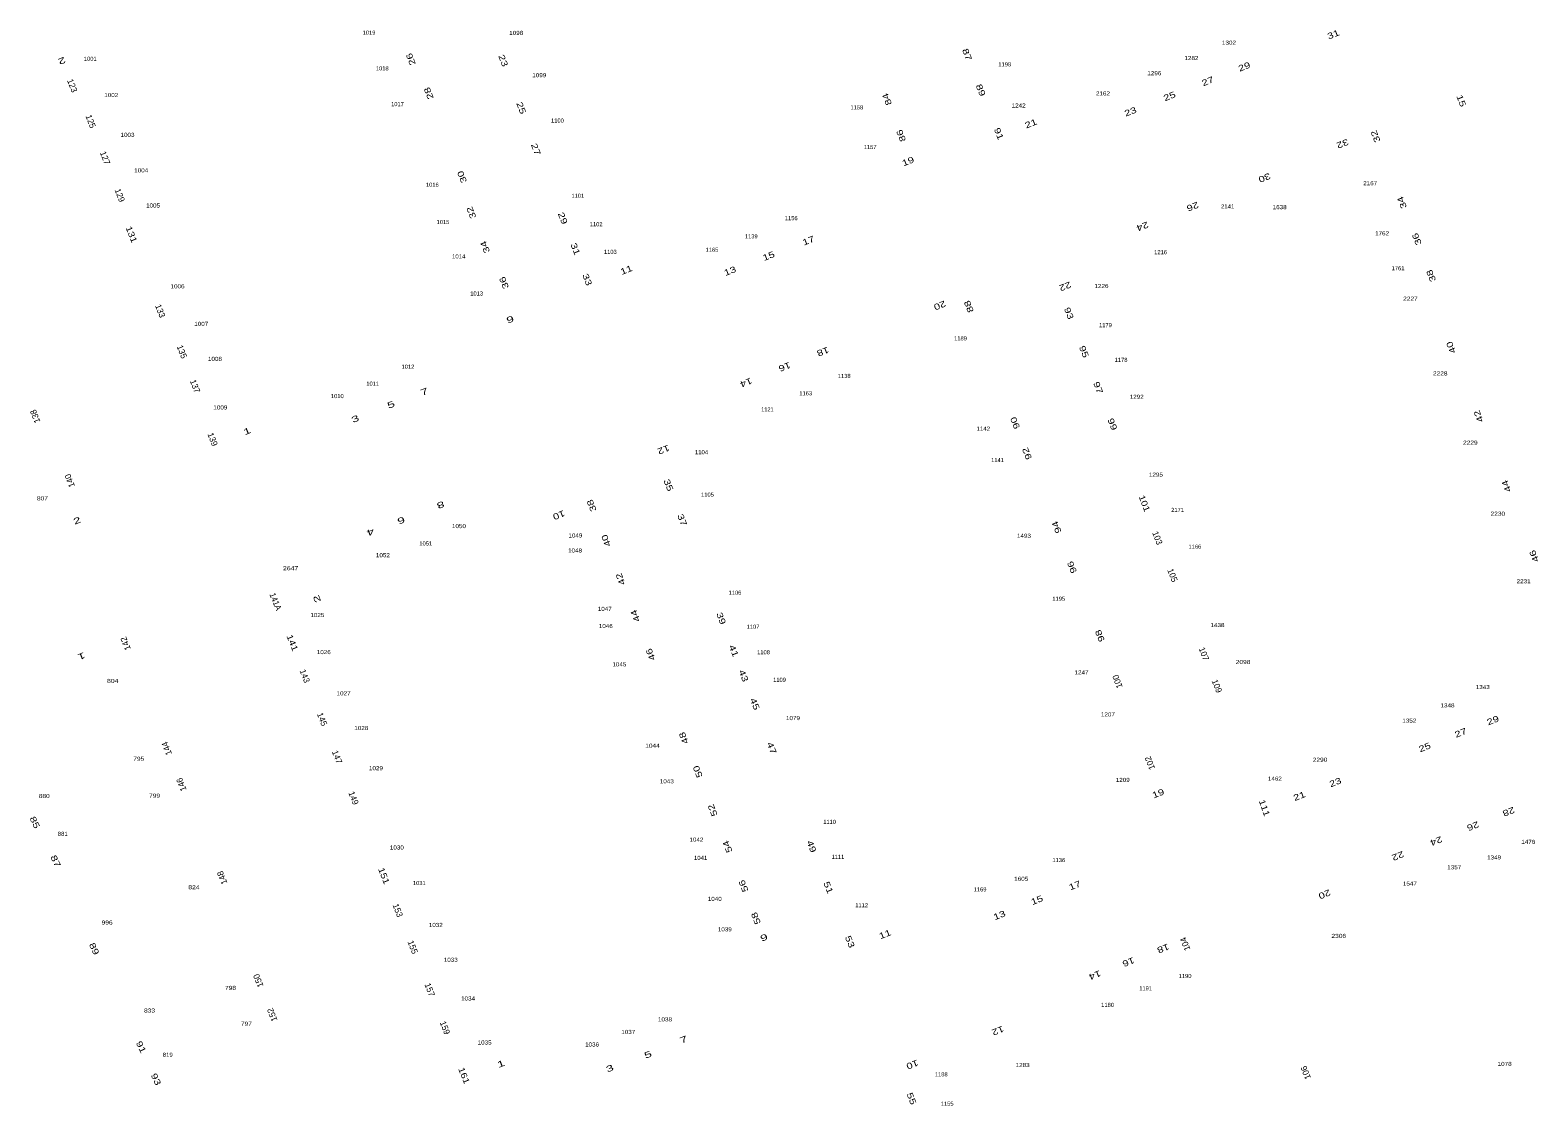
# Model space of a CAD drawing. Extents: x -828673 to -815583, y -1077737 to -1063807.
# Drawn here: x -821441.6 to -821072.8, y -1072104.4 to -1071841.3 of the extents above; entities that cross this region are included whole.
import ezdxf
from ezdxf.enums import TextEntityAlignment as Align

# ---------------------------------------------------------------- set-up
doc = ezdxf.new("R2010")
doc.units = 0
doc.header["$LTSCALE"] = 0.4
doc.layers.add('1', color=7, linetype='Continuous')
doc.layers.add('2', color=7, linetype='Continuous')

msp = doc.modelspace()

# ---------------------------------------------------------------- texts
at = {"layer": '1'}
for s, width, p in [('1019', 1.05, (-821358.676, -1071842.438)), ('1098', 1.15, (-821322.681, -1071842.501)), ('1302', 1.15, (-821148.373, -1071844.888)), ('1001', 1.05, (-821426.855, -1071848.838)), ('1018', 1.05, (-821355.448, -1071851.177)), ('1198', 1.05, (-821203.208, -1071850.196)), ('1282', 1.15, (-821157.545, -1071848.648)), ('1099', 1.15, (-821317.042, -1071852.844)), ('1296', 1.15, (-821166.627, -1071852.363)), ('1002', 1.15, (-821421.722, -1071857.701)), ('2162', 1.15, (-821179.183, -1071857.314)), ('1017', 1.05, (-821351.728, -1071859.925)), ('1158', 1.05, (-821239.376, -1071860.714)), ('1242', 1.15, (-821199.808, -1071860.268)), ('1100', 1.05, (-821312.602, -1071863.939)), ('1003', 1.15, (-821417.748, -1071867.433)), ('1157', 1.05, (-821236.132, -1071870.425)), ('1004', 1.15, (-821414.395, -1071876.13)), ('1016', 1.05, (-821343.2, -1071879.639)), ('2167', 1.15, (-821113.836, -1071879.273)), ('1005', 1.15, (-821411.5, -1071884.718)), ('1156', 1.05, (-821255.43, -1071887.812)), ('2141', 1.1, (-821148.692, -1071884.94)), ('1638', 1.15, (-821135.975, -1071885.124)), ('1015', 1.05, (-821340.598, -1071888.764)), ('1102', 1.05, (-821303.131, -1071889.296)), ('1762', 1.15, (-821110.933, -1071891.535)), ('1165', 1.05, (-821274.809, -1071895.536)), ('1139', 1.05, (-821265.198, -1071892.245)), ('1014', 1.1, (-821336.749, -1071897.171)), ('1103', 1.05, (-821299.671, -1071896.049)), ('1216', 1.05, (-821165.095, -1071896.142)), ('1761', 1.05, (-821107.016, -1071900.063)), ('1006', 1.15, (-821405.508, -1071904.477)), ('1013', 1.05, (-821332.361, -1071906.239)), ('1226', 1.15, (-821179.548, -1071904.408)), ('2227', 1.2, (-821103.984, -1071907.495)), ('1007', 1.15, (-821399.713, -1071913.671)), ('1179', 1.05, (-821178.581, -1071913.983)), ('1189', 1.05, (-821214.032, -1071917.207)), ('1008', 1.15, (-821396.369, -1071922.226)), ('1012', 1.05, (-821349.164, -1071924.144)), ('1178', 1.05, (-821174.757, -1071922.465)), ('1138', 1.05, (-821242.466, -1071926.4)), ('2228', 1.2, (-821096.704, -1071925.796)), ('1010', 1.05, (-821366.44, -1071931.337)), ('1163', 1.05, (-821251.869, -1071930.649)), ('1292', 1.15, (-821170.932, -1071931.5)), ('1009', 1.15, (-821395.044, -1071934.112)), ('1142', 1.1, (-821208.442, -1071939.285)), ('2229', 1.2, (-821089.341, -1071942.722)), ('1104', 1.1, (-821277.375, -1071945.06)), ('1295', 1.15, (-821166.236, -1071950.549)), ('807', 1.2, (-821438.554, -1071956.347)), ('1105', 1.05, (-821275.916, -1071955.437)), ('2171', 1.05, (-821160.938, -1071959.169)), ('2230', 1.2, (-821082.614, -1071960.101)), ('1050', 1.15, (-821336.695, -1071963.133)), ('1049', 1.15, (-821308.221, -1071965.424)), ('1493', 1.15, (-821198.51, -1071965.495)), ('1051', 1.05, (-821344.808, -1071967.378)), ('1048', 1.15, (-821308.299, -1071969.09)), ('1166', 1.05, (-821156.699, -1071968.158)), ('1052', 1.15, (-821355.291, -1071970.25)), ('2647', 1.25, (-821377.862, -1071973.433)), ('2231', 1.15, (-821076.307, -1071976.618)), ('1106', 1.05, (-821269.183, -1071979.421)), ('1047', 1.15, (-821301.031, -1071983.375)), ('1195', 1.05, (-821189.997, -1071980.891)), ('1025', 1.15, (-821371.31, -1071984.893)), ('1046', 1.15, (-821300.782, -1071987.579)), ('1107', 1.05, (-821264.765, -1071987.747)), ('1438', 1.15, (-821151.179, -1071987.34)), ('1026', 1.15, (-821369.749, -1071993.951)), ('1108', 1.05, (-821262.201, -1071993.981)), ('1045', 1.15, (-821297.454, -1071996.943)), ('1247', 1.15, (-821184.436, -1071998.922)), ('2098', 1.2, (-821144.913, -1071996.375)), ('804', 1.25, (-821421.362, -1072001.001)), ('1109', 1.05, (-821258.297, -1072000.728)), ('1343', 1.15, (-821086.3, -1072002.502)), ('1027', 1.15, (-821364.891, -1072004.029)), ('1207', 1.15, (-821177.976, -1072009.186)), ('1348', 1.15, (-821094.916, -1072006.973)), ('1028', 1.15, (-821360.564, -1072012.519)), ('1079', 1.15, (-821254.991, -1072010.09)), ('1352', 1.15, (-821104.269, -1072010.707)), ('1044', 1.2, (-821289.353, -1072016.842)), ('795', 1.2, (-821415.002, -1072020.029)), ('2290', 1.2, (-821126.092, -1072020.284)), ('1029', 1.15, (-821356.986, -1072022.342)), ('1043', 1.15, (-821285.858, -1072025.541)), ('1209', 1.15, (-821174.348, -1072025.205)), ('1462', 1.15, (-821137.15, -1072024.894)), ('880', 1.2, (-821438.114, -1072029.147)), ('799', 1.2, (-821411.121, -1072029.06)), ('881', 1.1, (-821433.579, -1072038.397)), ('1030', 1.15, (-821351.878, -1072041.738)), ('1042', 1.15, (-821278.619, -1072039.816)), ('1476', 1.15, (-821075.162, -1072040.36)), ('1041', 1.1, (-821277.584, -1072044.274)), ('1111', 0.9, (-821244, -1072044.024)), ('1136', 1.05, (-821189.994, -1072044.815)), ('1357', 1.15, (-821093.279, -1072046.576)), ('1349', 1.15, (-821083.539, -1072044.17)), ('1031', 1.05, (-821346.387, -1072050.436)), ('1605', 1.15, (-821199.183, -1072049.392)), ('824', 1.25, (-821401.491, -1072051.458)), ('1169', 1.05, (-821209.239, -1072051.996)), ('1547', 1.15, (-821104.125, -1072050.57)), ('1040', 1.15, (-821274.131, -1072054.305)), ('996', 1.2, (-821422.728, -1072060.096)), ('1032', 1.15, (-821342.351, -1072060.675)), ('1039', 1.15, (-821271.677, -1072061.755)), ('2306', 1.2, (-821121.52, -1072063.362)), ('1033', 1.15, (-821338.691, -1072069.207)), ('798', 1.2, (-821392.557, -1072076.079)), ('1190', 1.05, (-821159.105, -1072073.164)), ('1034', 1.15, (-821334.466, -1072078.662)), ('833', 1.2, (-821412.355, -1072081.62)), ('1180', 1.05, (-821178.056, -1072080.233)), ('797', 1.2, (-821388.676, -1072084.848)), ('1037', 1.15, (-821295.281, -1072086.847)), ('1038', 1.15, (-821286.3, -1072083.77)), ('1035', 1.15, (-821330.406, -1072089.432)), ('1036', 1.15, (-821304.139, -1072089.925)), ('819', 1.1, (-821407.907, -1072092.44)), ('1078', 1.15, (-821080.947, -1072094.671)), ('1188', 1.05, (-821218.736, -1072097.216)), ('1283', 1.15, (-821198.834, -1072094.948)), ('1155', 1.05, (-821217.284, -1072104.417))]:
    msp.add_text(s, height=1, dxfattribs=dict(at, width=width)).set_placement(p, align=Align.CENTER)
for s, p in [('1101', (-821307.609, -1071882.334)), ('1011', (-821357.789, -1071928.273)), ('1121', (-821261.254, -1071934.595)), ('1141', (-821204.978, -1071946.991)), ('1110', (-821246.042, -1072035.47)), ('1112', (-821238.203, -1072055.86)), ('1191', (-821168.746, -1072076.17))]:
    msp.add_text(s, height=1, dxfattribs=at).set_placement(p, align=Align.CENTER)
at = {"layer": '2'}
for s, rotation, width, p in [('31', 21.91, 1.35, (-821122.5759, -1071843.0675)), ('87', 291.612, 1.35, (-821213.1119, -1071847.5658)), ('2', 201.854, 1.65, (-821434.0593, -1071848.1341)), ('26', 111.307, 1.35, (-821347.7676, -1071848.1805)), ('23', 291.4, 1.35, (-821326.5503, -1071849.0453)), ('29', 21.878, 1.35, (-821144.3525, -1071850.9592)), ('27', 21.908, 1.35, (-821153.2858, -1071854.5225)), ('28', 111.366, 1.35, (-821343.3849, -1071856.5152)), ('84', 111.699, 1.35, (-821231.3212, -1071857.9743)), ('89', 291.69, 1.35, (-821209.77, -1071856.2768)), ('25', 21.865, 1.35, (-821162.6348, -1071858.1937)), ('15', 291.488, 1.35, (-821092.251, -1071858.8678)), ('25', 291.631, 1.35, (-821322.1484, -1071860.6285)), ('23', 21.315, 1.35, (-821172.2096, -1071861.9563)), ('21', 21.878, 1.35, (-821196.5365, -1071864.8572)), ('86', 111.334, 1.35, (-821227.8612, -1071866.8719)), ('91', 291.552, 1.35, (-821205.3375, -1071866.943)), ('32', 201.845, 1.35, (-821120.8469, -1071868.415)), ('32', 111.531, 1.35, (-821111.8282, -1071867.0482)), ('27', 291.657, 1.35, (-821318.5638, -1071870.7392)), ('19', 21.763, 1.35, (-821226.5776, -1071874.1151)), ('30', 111.53, 1.35, (-821335.2402, -1071876.9522)), ('30', 201.754, 1.35, (-821139.9455, -1071876.7557)), ('26', 201.801, 1.35, (-821157.524, -1071883.7998)), ('34', 111.633, 1.35, (-821105.3786, -1071883.2295)), ('32', 111.778, 1.35, (-821332.9712, -1071885.7028)), ('29', 291.829, 1.35, (-821311.9884, -1071887.5971)), ('131', 291.645, 1.25, (-821417.4698, -1071891.5749)), ('24', 201.251, 1.35, (-821169.7807, -1071888.638)), ('36', 111.567, 1.35, (-821101.7389, -1071892.1722)), ('34', 111.848, 1.35, (-821329.6191, -1071894.1101)), ('31', 291.488, 1.35, (-821308.899, -1071895.1208)), ('17', 21.485, 1.35, (-821250.9452, -1071893.5011)), ('15', 21.571, 1.35, (-821260.6842, -1071897.263)), ('36', 111.506, 1.35, (-821324.9804, -1071902.8485)), ('33', 291.674, 1.35, (-821306.0084, -1071902.616)), ('11', 21.48, 1.35, (-821295.4761, -1071900.6742)), ('13', 21.501, 1.35, (-821270.1244, -1071900.9377)), ('38', 111.807, 1.35, (-821098.2459, -1071901.1261)), ('22', 201.151, 1.35, (-821188.7014, -1071903.3115)), ('20', 201.294, 1.35, (-821219.3451, -1071907.963)), ('88', 112.213, 1.35, (-821211.3021, -1071908.6645)), ('93', 291.259, 1.35, (-821188.2008, -1071910.8476)), ('9', 19.822, 1.65, (-821323.9123, -1071912.7973)), ('18', 201.492, 1.35, (-821247.9327, -1071919.2571)), ('95', 291.746, 1.35, (-821184.5125, -1071920.2386)), ('40', 112.82, 1.35, (-821093.3572, -1071918.6659)), ('16', 201.364, 1.35, (-821257.2968, -1071922.9929)), ('14', 201.737, 1.35, (-821266.7217, -1071926.8243)), ('97', 291.522, 1.35, (-821181.0582, -1071929.0414)), ('7', 20.452, 1.65, (-821344.8966, -1071930.4492)), ('5', 21.756, 1.65, (-821353.0265, -1071933.6146)), ('42', 111.621, 1.35, (-821086.6333, -1071935.4983)), ('1', 22.65, 1.65, (-821388.2288, -1071940.0956)), ('3', 22.629, 1.65, (-821361.7636, -1071937.0868)), ('90', 111.497, 1.35, (-821199.9882, -1071937.1283)), ('99', 291.476, 1.35, (-821177.5553, -1071937.9869)), ('12', 201.588, 1.35, (-821286.9051, -1071943.2446)), ('92', 111.524, 1.35, (-821197.0688, -1071944.6247)), ('35', 291.718, 1.35, (-821286.1342, -1071952.88)), ('44', 111.702, 1.35, (-821079.8152, -1071952.6023)), ('8', 201.233, 1.65, (-821341.4389, -1071956.7601)), ('38', 111.603, 1.35, (-821303.5499, -1071957.3571)), ('101', 291.411, 1.25, (-821169.7398, -1071957.3527)), ('2', 21.486, 1.65, (-821429.8252, -1071961.9808)), ('6', 201.219, 1.65, (-821351.0891, -1071960.547)), ('10', 201.497, 1.35, (-821312.5057, -1071959.2522)), ('37', 291.416, 1.35, (-821282.7837, -1071961.4026)), ('4', 201.216, 1.65, (-821358.5771, -1071963.4189)), ('40', 111.642, 1.35, (-821300.0048, -1071965.9116)), ('94', 111.664, 1.35, (-821189.8193, -1071962.6299)), ('96', 111.728, 1.35, (-821186.0791, -1071972.4221)), ('46', 111.633, 1.35, (-821073.0486, -1071969.7175)), ('42', 111.498, 1.35, (-821296.4753, -1071975.3294)), ('141A', 292.085, 0.95, (-821382.2293, -1071981.382)), ('2', 111.686, 1.65, (-821370.7083, -1071980.1451)), ('44', 111.44, 1.35, (-821292.8559, -1071984.3196)), ('39', 291.269, 1.35, (-821273.2515, -1071985.4704)), ('141', 292.087, 1.25, (-821378.1256, -1071991.4505)), ('98', 111.548, 1.35, (-821179.2544, -1071989.191)), ('1', 201.51, 1.65, (-821429.2535, -1071993.7545)), ('46', 111.801, 1.35, (-821289.1138, -1071993.768)), ('41', 291.801, 1.35, (-821270.1652, -1071993.416)), ('43', 291.55, 1.35, (-821267.7775, -1071999.494)), ('45', 291.86, 1.35, (-821265.0156, -1072006.3957)), ('27', 21.444, 1.35, (-821091.4282, -1072013.8772)), ('29', 21.439, 1.35, (-821083.5496, -1072010.8351)), ('48', 111.657, 1.35, (-821281.0112, -1072014.2088)), ('47', 291.439, 1.35, (-821260.8821, -1072017.1784)), ('25', 21.827, 1.35, (-821100.2289, -1072017.4244)), ('50', 111.919, 1.35, (-821277.6007, -1072022.407)), ('19', 21.422, 1.35, (-821165.4094, -1072028.7175)), ('23', 22.019, 1.35, (-821122.0987, -1072025.9877)), ('52', 111.78, 1.35, (-821273.9403, -1072031.8558)), ('111', 289.354, 1.25, (-821140.4079, -1072031.805)), ('21', 21.267, 1.35, (-821130.8915, -1072029.3566)), ('85', 295.286, 1.35, (-821441.0875, -1072035.4276)), ('28', 201.517, 1.35, (-821080.2334, -1072031.8017)), ('24', 201.589, 1.35, (-821097.95, -1072038.9806)), ('26', 201.578, 1.35, (-821088.9707, -1072035.3321)), ('54', 111.759, 1.35, (-821270.3256, -1072040.766)), ('49', 291.516, 1.35, (-821251.1453, -1072041.2544)), ('22', 201.488, 1.35, (-821107.3138, -1072042.613)), ('87', 295.396, 1.35, (-821435.9839, -1072044.8943)), ('151', 291.409, 1.25, (-821355.7269, -1072048.4367)), ('56', 111.812, 1.35, (-821266.414, -1072050.3802)), ('17', 21.516, 1.35, (-821185.7886, -1072051.2073)), ('51', 291.493, 1.35, (-821247.0289, -1072051.3157)), ('15', 21.438, 1.35, (-821195.0556, -1072054.7982)), ('20', 202.416, 1.35, (-821125.269, -1072052.0003)), ('13', 21.601, 1.35, (-821204.2451, -1072058.5051)), ('58', 111.727, 1.35, (-821263.377, -1072058.2871)), ('9', 21.959, 1.65, (-821261.8185, -1072063.9594)), ('53', 291.815, 1.35, (-821241.7649, -1072064.5648)), ('11', 21.196, 1.35, (-821232.2227, -1072063.1512)), ('89', 295.364, 1.35, (-821426.5737, -1072066.3337)), ('18', 201.598, 1.35, (-821164.7209, -1072065.2358)), ('14', 202.024, 1.35, (-821181.4262, -1072071.7794)), ('16', 201.47, 1.35, (-821173.2055, -1072068.5704)), ('12', 201.991, 1.35, (-821205.1422, -1072085.3384)), ('91', 295.482, 1.35, (-821415.0876, -1072090.3548)), ('7', 21.684, 1.65, (-821281.4561, -1072088.8977)), ('1', 21.404, 1.65, (-821326.1487, -1072094.8501)), ('5', 21.05, 1.65, (-821290.1899, -1072092.5956)), ('10', 201.882, 1.35, (-821226.0685, -1072093.6489)), ('93', 295.125, 1.35, (-821411.4486, -1072098.2401)), ('161', 291.58, 1.25, (-821336.137, -1072097.2926)), ('3', 21.374, 1.65, (-821299.5348, -1072095.9577)), ('55', 291.564, 1.35, (-821226.6902, -1072102.9278))]:
    msp.add_text(s, height=1.5, rotation=rotation, dxfattribs=dict(at, width=width)).set_placement(p, align=Align.CENTER)
for s, rotation, p in [('123', 291.843, (-821431.9471, -1071855.174)), ('125', 291.419, (-821427.4347, -1071863.9131)), ('127', 291.565, (-821423.9159, -1071872.8578)), ('129', 291.534, (-821420.3175, -1071881.9857)), ('133', 291.409, (-821410.4337, -1071910.2747)), ('135', 291.577, (-821405.1343, -1071920.2557)), ('137', 291.655, (-821401.9059, -1071928.7042)), ('138', 111.306, (-821439.6283, -1071935.5285)), ('139', 291.699, (-821397.6118, -1071941.6907)), ('140', 110.894, (-821431.1776, -1071951.2715)), ('103', 291.614, (-821166.5583, -1071965.8077)), ('105', 291.833, (-821162.8723, -1071974.9351)), ('142', 111.592, (-821417.5241, -1071991.098)), ('107', 291.653, (-821155.1875, -1071994.1618)), ('143', 291.471, (-821375.0735, -1071999.57)), ('100', 111.017, (-821174.94, -1072000.387)), ('109', 292.049, (-821152.0072, -1072002.0449)), ('145', 291.701, (-821370.839, -1072010.1477)), ('144', 111.658, (-821407.4579, -1072016.7568)), ('147', 291.77, (-821367.1791, -1072019.3868)), ('102', 111.441, (-821167.0127, -1072020.3117)), ('146', 111.669, (-821403.8822, -1072025.5699)), ('149', 291.538, (-821363.1424, -1072029.4167)), ('148', 112.006, (-821393.9046, -1072048.3605)), ('153', 291.598, (-821352.3358, -1072056.8869)), ('155', 291.58, (-821348.6743, -1072065.8772)), ('104', 111.516, (-821158.3778, -1072064.5756)), ('150', 111.801, (-821385.0568, -1072073.5475)), ('157', 291.77, (-821344.5211, -1072076.2928)), ('152', 111.837, (-821381.6548, -1072081.881)), ('159', 291.542, (-821340.8013, -1072085.6156)), ('106', 111.524, (-821128.898, -1072096.0427))]:
    msp.add_text(s, height=1.5, rotation=rotation, dxfattribs=at).set_placement(p, align=Align.CENTER)

doc.saveas('drawing.dxf')
